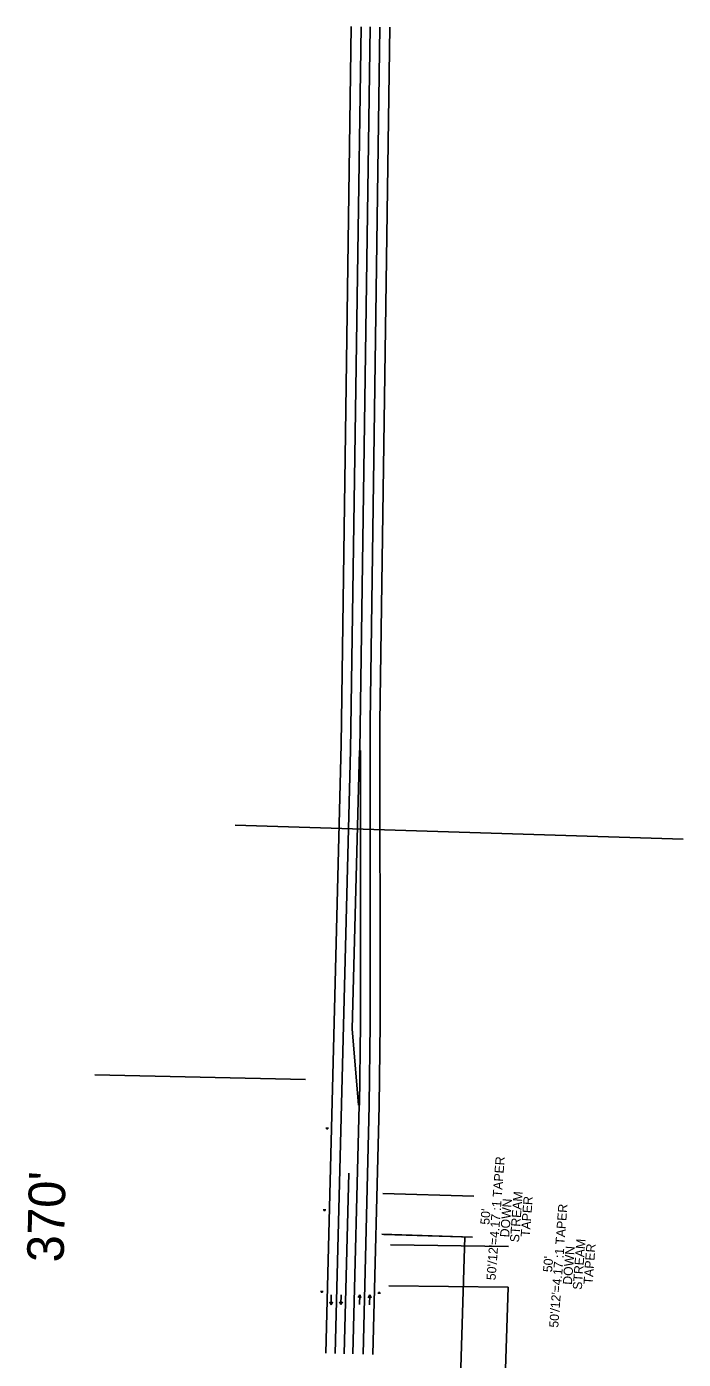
# Model space of a CAD drawing. Extents: x 1650647 to 1653016, y 602856 to 611467.
# Drawn here: x 1652212 to 1653016, y 609813 to 611444 of the extents above; entities that cross this region are included whole.
import ezdxf

# ---------------------------------------------------------------- set-up
doc = ezdxf.new("R2010")
doc.units = 0
for name, color, linetype in [('CM_Corridor_Design', 7, 'Continuous'), ('PF_P_Grade_Line', 7, 'Continuous'), ('PF_X_Ground_Line', 7, 'Continuous'), ('PF_X_Ground_Line_RT', 7, 'Continuous'), ('PV_P_Curb', 7, 'Continuous'), ('SC_Scratch1', 7, 'Continuous'), ('UT_X_Water', 7, 'Continuous')]:
    doc.layers.add(name, color=color, linetype=linetype)

msp = doc.modelspace()

# ---------------------------------------------------------------- linework, layer by layer
at = {"layer": 'CM_Corridor_Design'}
for p, q in [((1652584.7, 609879.6), (1652584.9, 609891.5)), ((1652596.8, 609879.8), (1652597, 609891.7)), ((1652619.7, 609891.7), (1652617.9, 609888.4)), ((1652619.7, 609891.7), (1652619.3, 609879.8)), ((1652619.7, 609891.7), (1652621.3, 609888.2)), ((1652632, 609891.5), (1652630.2, 609888.2)), ((1652632, 609891.5), (1652631.6, 609879.6)), ((1652632, 609891.5), (1652633.6, 609888)), ((1652584.7, 609879.6), (1652583, 609883)), ((1652584.7, 609879.6), (1652586.5, 609883)), ((1652596.8, 609879.8), (1652595.1, 609883.2)), ((1652596.8, 609879.8), (1652598.6, 609883.2))]:
    msp.add_line(p, q, dxfattribs=at)
at = {"layer": 'PF_P_Grade_Line'}
for p, q in [((1652608.4, 610558.3), (1652621.5, 611443.9)), ((1652632.5, 610592.5), (1652644.4, 611443.6)), ((1652632.7, 610223.6), (1652632.5, 610592.5)), ((1652589.8, 609819.9), (1652608.4, 610558.3)), ((1652631.4, 610123.7), (1652632.7, 610223.4)), ((1652623.8, 609818.9), (1652631.4, 610123.5))]:
    msp.add_line(p, q, dxfattribs=at)
at = {"layer": 'PF_X_Ground_Line'}
for p, q in [((1652581.6, 610095.7), (1652578.4, 610095.8)), ((1652580, 610095.8), (1652579.9, 610094.2)), ((1652580, 610095.8), (1652580, 610095.8)), ((1652578.4, 609995.8), (1652575.2, 609995.9)), ((1652576.8, 609995.8), (1652576.7, 609994.2)), ((1652576.8, 609995.8), (1652576.8, 609995.8)), ((1652575.1, 609895.8), (1652571.9, 609895.9)), ((1652573.5, 609895.9), (1652573.5, 609894.3)), ((1652573.5, 609895.9), (1652573.5, 609895.9)), ((1652642, 609893.7), (1652645.2, 609893.6)), ((1652643.6, 609893.6), (1652643.7, 609895.2)), ((1652643.6, 609893.6), (1652643.6, 609893.6))]:
    msp.add_line(p, q, dxfattribs=at)
at = {"layer": 'PF_X_Ground_Line_RT'}
for p, q in [((1653015.5, 610449.5), (1652467.5, 610466.6)), ((1652759.1, 610012.3), (1652648.2, 610015.8)), ((1652757.5, 609962.4), (1652646.6, 609965.8)), ((1652757.5, 609962.4), (1652649.4, 609965.7)), ((1652801.8, 609951), (1652657.4, 609952.9)), ((1652707.1, 608643.3), (1652748.3, 609962.6)), ((1652801.2, 609901), (1652655.2, 609902.9)), ((1652761.8, 608641.6), (1652801.2, 609901))]:
    msp.add_line(p, q, dxfattribs=at)
at = {"layer": 'PV_P_Curb'}
for p, q in [((1652620, 610558.2), (1652632.4, 611443.8)), ((1652610.5, 610217.3), (1652619.5, 610558.2)), ((1652620.5, 610558.2), (1652620.7, 610223.6)), ((1652618.4, 610123.8), (1652610.5, 610217.3)), ((1652619.4, 610123.8), (1652620.7, 610223.6)), ((1652611.3, 609819.3), (1652618.9, 610123.8))]:
    msp.add_line(p, q, dxfattribs=at)
at = {"layer": 'SC_Scratch1'}
for p, q in [((1652597.1, 610565.3), (1652609.4, 611444.1)), ((1652644.5, 610592.4), (1652656.4, 611443.4)), ((1652644.5, 610592.4), (1652644.7, 610223.6)), ((1652578.3, 609820.3), (1652597.1, 610565.3)), ((1652643.4, 610123.5), (1652644.7, 610223.3)), ((1652635.7, 609818.5), (1652643.4, 610123.2)), ((1652600.8, 609819.6), (1652606.3, 610040.5))]:
    msp.add_line(p, q, dxfattribs=at)
at = {"layer": 'UT_X_Water'}
msp.add_line((1652553.4, 610155.1), (1652295.9, 610161.1), dxfattribs=at)

# ---------------------------------------------------------------- texts
at = {"layer": 'PF_X_Ground_Line_RT'}
for s, p in [("50'/12'=4.17 :1 TAPER", (1652785.8, 609909.3)), ('STREAM', (1652814.5, 609955.7)), ('DOWN', (1652802.4, 609961.8)), ('TAPER', (1652827.7, 609962.3)), ("50'/12'=4.17 :1 TAPER", (1652862.5, 609851.2)), ("50' ", (1652778.3, 609977.2)), ('STREAM', (1652891.3, 609897.6)), ('TAPER', (1652904.5, 609904.2)), ("50' ", (1652855, 609919.1)), ('DOWN', (1652879.2, 609903.7))]:
    msp.add_text(s, height=11.2, rotation=85.6823, dxfattribs=at).set_placement(p)
at = {"layer": 'UT_X_Water'}
msp.add_text("370'", height=44.8, rotation=88.672, dxfattribs=at).set_placement((1652257.6, 609931.1))

doc.saveas('drawing.dxf')
